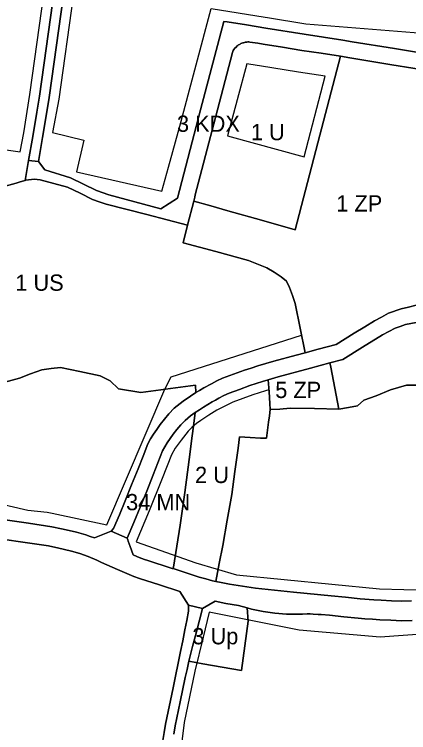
# Model space of a CAD drawing. Extents: x -294445 to -292055, y 21869 to 23693.
# Drawn here: x -293330.1 to -293087.7, y 22598.3 to 23039.5 of the extents above; entities that cross this region are included whole.
import ezdxf

# ---------------------------------------------------------------- set-up
doc = ezdxf.new("R2010")
doc.units = 0
for name, color, linetype in [('linie_rozgraniczajace', 7, 'Continuous'), ('linie_zabudowy_nieprzekraczalne', 7, 'Continuous'), ('oznaczenia_przeznaczen', 7, 'Continuous')]:
    doc.layers.add(name, color=color, linetype=linetype)

msp = doc.modelspace()

# ---------------------------------------------------------------- linework, layer by layer
at = {"layer": 'linie_rozgraniczajace'}
for points in [[(-293299.907, 23051.384), (-293308.794, 22988.328), (-293310.369, 22978.417), (-293312.858, 22963.757), (-293315.346, 22949.098), (-293321.333, 22949.685), (-293318.811, 22964.538), (-293316.29, 22979.39), (-293315.505, 22984.33), (-293314.72, 22989.27), (-293296.941, 23115.409)], [(-293296.941, 23115.409), (-293314.72, 22989.27), (-293315.505, 22984.33)], [(-293315.346, 22949.098), (-293312.858, 22963.757), (-293310.369, 22978.417), (-293308.794, 22988.328), (-293299.907, 23051.384)], [(-293072.139, 23004.28), (-293098.053, 23008.549), (-293123.966, 23012.819), (-293129.58, 23013.76), (-293141.588, 23015.576), (-293153.433, 23017.368), (-293165.307, 23019.257), (-293177.181, 23021.146), (-293180.425, 23021.669), (-293185.357, 23022.463), (-293185.862, 23022.492), (-293186.493, 23022.495), (-293187.11, 23022.463), (-293187.619, 23022.41), (-293188.16, 23022.327), (-293188.712, 23022.213), (-293189.312, 23022.054), (-293189.749, 23021.916), (-293190.346, 23021.692), (-293190.816, 23021.488), (-293191.304, 23021.246), (-293191.762, 23020.991), (-293192.213, 23020.71), (-293192.663, 23020.399), (-293193.264, 23019.925), (-293193.841, 23019.401), (-293194.562, 23018.626), (-293195.179, 23017.82), (-293195.5, 23017.331), (-293196.032, 23016.062), (-293207.469, 22972.314), (-293218.907, 22928.567), (-293219.18, 22927.093), (-293219.791, 22924.751), (-293223.618, 22910.077), (-293248.678, 22916.484), (-293273.738, 22922.891), (-293277.877, 22924.344), (-293282.015, 22925.798), (-293289.706, 22929.574), (-293297.396, 22933.35), (-293305.808, 22935.631), (-293314.22, 22937.911), (-293318.038, 22938.254), (-293323.044, 22937.614), (-293323.401, 22937.5), (-293321.333, 22949.685), (-293315.346, 22949.098), (-293311.352, 22943.884), (-293295.567, 22939.136), (-293279.691, 22931.341), (-293271.954, 22928.623), (-293256.017, 22924.284), (-293240.08, 22919.945), (-293229.779, 22926.514), (-293215.575, 22980.847), (-293201.37, 23035.18), (-293199.29, 23034.84), (-293187.445, 23032.93), (-293175.6, 23031.02), (-293151.9, 23027.25), (-293140.035, 23025.455), (-293128.17, 23023.66), (-293122.34, 23022.686), (-293096.315, 23018.398), (-293070.29, 23014.11)], [(-293070.29, 23014.11), (-293096.315, 23018.398), (-293122.34, 23022.686), (-293128.17, 23023.66), (-293140.035, 23025.455), (-293151.9, 23027.25), (-293175.6, 23031.02), (-293187.445, 23032.93), (-293199.29, 23034.84), (-293201.37, 23035.18), (-293215.575, 22980.847), (-293229.779, 22926.514), (-293240.08, 22919.945)], [(-293083.185, 22860.868), (-293087.721, 22859.716), (-293092.258, 22858.563), (-293100.066, 22855.873), (-293104.396, 22853.543), (-293108.726, 22851.213), (-293114.654, 22847.572), (-293121.122, 22843.625), (-293126.692, 22840.191), (-293132.263, 22836.757), (-293137.795, 22835.263), (-293143.327, 22833.768), (-293151.408, 22831.585), (-293154.424, 22846.682), (-293157.44, 22861.778), (-293159.206, 22866.785), (-293160.972, 22871.791), (-293162.756, 22875.604), (-293165.988, 22878.344), (-293170.455, 22881.018), (-293174.922, 22883.692), (-293186.082, 22888.209), (-293206.167, 22893.715), (-293226.252, 22899.222), (-293223.618, 22910.077), (-293219.791, 22924.751), (-293209.37, 22921.816), (-293198.95, 22918.88), (-293178.196, 22913.033), (-293157.442, 22907.187), (-293143.511, 22960.473), (-293129.58, 23013.76), (-293123.966, 23012.819), (-293098.053, 23008.549), (-293072.139, 23004.28)], [(-293315.505, 22984.33), (-293316.29, 22979.39), (-293318.811, 22964.538), (-293321.333, 22949.685), (-293323.401, 22937.5), (-293325.094, 22936.964), (-293327.145, 22936.313), (-293328.905, 22935.847), (-293344.144, 22931.667)], [(-293240.08, 22919.945), (-293256.017, 22924.284), (-293271.954, 22928.623), (-293279.691, 22931.341), (-293295.567, 22939.136), (-293311.352, 22943.884), (-293315.346, 22949.098)], [(-293344.144, 22931.667), (-293328.905, 22935.847), (-293327.145, 22936.313), (-293325.094, 22936.964), (-293323.401, 22937.5), (-293323.044, 22937.614), (-293318.038, 22938.254), (-293314.22, 22937.911), (-293305.808, 22935.631), (-293297.396, 22933.35), (-293289.706, 22929.574), (-293282.015, 22925.798), (-293277.877, 22924.344), (-293273.738, 22922.891), (-293248.678, 22916.484), (-293223.618, 22910.077), (-293226.252, 22899.222), (-293206.167, 22893.715), (-293186.082, 22888.209), (-293174.922, 22883.692), (-293170.455, 22881.018), (-293165.988, 22878.344), (-293162.756, 22875.604), (-293160.972, 22871.791), (-293159.206, 22866.785), (-293157.44, 22861.778), (-293154.424, 22846.682), (-293151.408, 22831.585), (-293156.938, 22830.092), (-293170.549, 22826.415), (-293175.484, 22824.977), (-293180.419, 22823.54), (-293184.509, 22822.216), (-293188.598, 22820.893), (-293195.387, 22818.436), (-293202.175, 22815.98), (-293205.576, 22814.306), (-293208.978, 22812.632), (-293213.612, 22810.11), (-293216.368, 22808.453), (-293218.479, 22807.184), (-293218.736, 22811.745), (-293227.936, 22810.516), (-293237.137, 22809.286), (-293240.04, 22808.898), (-293246.17, 22808.079), (-293252.3, 22807.26), (-293266.04, 22809.54), (-293271.31, 22814.28), (-293276.85, 22817.26), (-293277.457, 22817.39), (-293289.867, 22820.05), (-293301.67, 22822.58), (-293307.475, 22821.905), (-293313.28, 22821.23), (-293320.105, 22818.67), (-293326.93, 22816.11), (-293336.05, 22813.51)], [(-293075.467, 22851.666), (-293089.654, 22848.884), (-293092.848, 22847.783), (-293096.041, 22846.682), (-293099.889, 22844.612), (-293103.736, 22842.542), (-293115.998, 22835.011), (-293128.26, 22827.48), (-293136.065, 22825.372), (-293148.053, 22822.133), (-293167.847, 22816.787), (-293174.092, 22814.967), (-293177.48, 22813.98), (-293181.42, 22812.705), (-293185.36, 22811.43), (-293191.735, 22809.128), (-293198.109, 22806.827), (-293201.246, 22805.287), (-293204.383, 22803.747), (-293206.489, 22802.601), (-293208.595, 22801.455), (-293211.17, 22799.868), (-293213.746, 22798.28), (-293216.359, 22796.627), (-293218.971, 22794.974), (-293221.86, 22792.792), (-293225.047, 22790.109), (-293227.792, 22787.436), (-293230.183, 22784.397), (-293232.453, 22781.514), (-293234.33, 22778.876), (-293236.207, 22776.238), (-293238.962, 22771.453), (-293241.85, 22764.004), (-293244.684, 22756.689), (-293248.759, 22746.687), (-293252.781, 22736.818), (-293256.753, 22727.285), (-293260.726, 22717.753), (-293270.514, 22722.067), (-293269.08, 22723.62), (-293265.555, 22732.12), (-293262.03, 22740.62), (-293258.03, 22750.435), (-293254.03, 22760.25), (-293251.02, 22768.015), (-293248.01, 22775.78), (-293246.322, 22778.712), (-293244.634, 22781.644), (-293242.547, 22784.576), (-293240.461, 22787.509), (-293237.851, 22790.824), (-293235.241, 22794.139), (-293231.765, 22797.526), (-293226.383, 22801.907), (-293221.896, 22805), (-293218.479, 22807.184), (-293216.368, 22808.453), (-293213.612, 22810.11), (-293208.978, 22812.632), (-293205.576, 22814.306), (-293202.175, 22815.98), (-293195.387, 22818.436), (-293188.598, 22820.893), (-293184.509, 22822.216), (-293180.419, 22823.54), (-293175.484, 22824.977), (-293170.549, 22826.415), (-293156.938, 22830.092), (-293151.408, 22831.585), (-293143.327, 22833.768), (-293137.795, 22835.263), (-293132.263, 22836.757), (-293126.692, 22840.191), (-293121.122, 22843.625), (-293114.654, 22847.572), (-293108.726, 22851.213), (-293104.396, 22853.543), (-293100.066, 22855.873), (-293092.258, 22858.563), (-293087.721, 22859.716), (-293083.185, 22860.868)], [(-293073.705, 22811.635), (-293088.99, 22811.74), (-293093.955, 22810.25), (-293098.92, 22808.76), (-293107.63, 22805.24), (-293115.26, 22802.57), (-293119.21, 22799.03), (-293124.787, 22798.069), (-293130.7, 22797.05), (-293133.128, 22809.866), (-293135.555, 22822.681), (-293136.065, 22825.372), (-293128.26, 22827.48), (-293115.998, 22835.011), (-293103.736, 22842.542), (-293099.889, 22844.612), (-293096.041, 22846.682), (-293092.848, 22847.783), (-293089.654, 22848.884), (-293075.467, 22851.666)], [(-293336.05, 22813.51), (-293326.93, 22816.11), (-293320.105, 22818.67), (-293313.28, 22821.23), (-293307.475, 22821.905), (-293301.67, 22822.58), (-293289.867, 22820.05), (-293277.457, 22817.39), (-293276.85, 22817.26), (-293271.31, 22814.28), (-293266.04, 22809.54), (-293252.3, 22807.26), (-293246.17, 22808.079), (-293240.04, 22808.898), (-293237.137, 22809.286), (-293227.936, 22810.516), (-293218.736, 22811.745), (-293218.479, 22807.184), (-293221.896, 22805), (-293226.383, 22801.907), (-293231.765, 22797.526), (-293235.241, 22794.139), (-293237.851, 22790.824), (-293240.461, 22787.509), (-293242.547, 22784.576), (-293244.634, 22781.644), (-293246.322, 22778.712), (-293248.01, 22775.78), (-293251.02, 22768.015), (-293254.03, 22760.25), (-293258.03, 22750.435), (-293262.03, 22740.62), (-293265.555, 22732.12), (-293269.08, 22723.62), (-293270.514, 22722.067), (-293280.834, 22717.853), (-293283.499, 22718.812), (-293286.164, 22719.771), (-293289.031, 22720.589), (-293291.898, 22721.408), (-293296.508, 22722.481), (-293301.118, 22723.555), (-293307.173, 22724.755), (-293321.52, 22726.874), (-293335.867, 22728.994)], [(-293085.91, 22679.252), (-293092.014, 22678.982), (-293098.318, 22679.308), (-293104.621, 22679.634), (-293109.18, 22679.939), (-293117.611, 22680.561), (-293126.439, 22681.427), (-293135.266, 22682.292), (-293158.562, 22684.617), (-293181.859, 22686.942), (-293189.874, 22688.208), (-293197.889, 22689.475), (-293203.056, 22690.554), (-293206.234, 22691.217), (-293204.112, 22702.249), (-293201.99, 22713.28), (-293199.235, 22728.89), (-293196.48, 22744.5), (-293194.47, 22758.75), (-293192.46, 22773), (-293191.66, 22779.94), (-293185.2, 22779.565), (-293178.74, 22779.19), (-293175, 22779.063), (-293174.424, 22783.988), (-293173.848, 22788.914), (-293173.341, 22792.8), (-293172.834, 22796.686), (-293167, 22796.99), (-293160.63, 22797.53), (-293145.665, 22797.29), (-293130.7, 22797.05), (-293124.787, 22798.069), (-293119.21, 22799.03), (-293115.26, 22802.57), (-293107.63, 22805.24), (-293098.92, 22808.76), (-293093.955, 22810.25), (-293088.99, 22811.74), (-293073.705, 22811.635)], [(-293335.867, 22728.994), (-293321.52, 22726.874), (-293307.173, 22724.755), (-293301.118, 22723.555), (-293296.508, 22722.481), (-293291.898, 22721.408), (-293289.031, 22720.589), (-293286.164, 22719.771), (-293283.499, 22718.812), (-293280.834, 22717.853), (-293270.514, 22722.067), (-293260.726, 22717.753), (-293260.391, 22716.791), (-293260.062, 22715.847), (-293258.934, 22712.607), (-293257.142, 22707.461), (-293254.754, 22706.424), (-293252.365, 22705.387), (-293249.567, 22704.424), (-293248.658, 22704.135), (-293232.999, 22699.147), (-293232.562, 22699.008), (-293216.43, 22693.869), (-293212.327, 22692.751), (-293208.224, 22691.633), (-293206.234, 22691.217), (-293203.056, 22690.554), (-293197.889, 22689.475), (-293189.874, 22688.208), (-293181.859, 22686.942), (-293158.562, 22684.617), (-293135.266, 22682.292), (-293126.439, 22681.427), (-293117.611, 22680.561), (-293109.18, 22679.939), (-293104.621, 22679.634), (-293098.318, 22679.308), (-293092.014, 22678.982), (-293085.91, 22679.252)], [(-293337.519, 22717.108), (-293323.368, 22715.017), (-293309.217, 22712.927), (-293306.431, 22712.375), (-293303.646, 22711.823), (-293299.277, 22710.805), (-293294.908, 22709.788), (-293289.846, 22708.342), (-293284.646, 22706.471), (-293279.467, 22704.171), (-293276.533, 22702.798), (-293266.623, 22698.495), (-293256.713, 22694.192), (-293253.258, 22693.004), (-293240.791, 22689.03), (-293228.323, 22685.055), (-293223.055, 22676.544), (-293223.01, 22672.81), (-293224.157, 22667.084), (-293225.304, 22661.357), (-293226.63, 22654.739), (-293227.955, 22648.12), (-293232.563, 22625.817), (-293237.17, 22603.514), (-293238.035, 22598.462), (-293238.9, 22593.41)], [(-293085.501, 22667.258), (-293092.059, 22666.968), (-293098.695, 22667.311), (-293105.332, 22667.654), (-293109.981, 22667.966), (-293114.629, 22668.277), (-293118.687, 22668.609), (-293127.567, 22669.48), (-293136.447, 22670.351), (-293141.395, 22670.752), (-293143.281, 22670.906), (-293146.343, 22671.154), (-293148.233, 22671.195), (-293150.123, 22671.236), (-293152.868, 22671.137), (-293155.612, 22671.039), (-293162.881, 22671.09), (-293170.004, 22671.678), (-293177.084, 22672.727), (-293184.226, 22674.155), (-293186.99, 22674.94), (-293192.322, 22676.446), (-293196.188, 22677.057), (-293200.053, 22677.668), (-293206.565, 22679.028), (-293214.541, 22674.444), (-293223.055, 22676.544), (-293228.323, 22685.055), (-293240.791, 22689.03), (-293253.258, 22693.004), (-293256.713, 22694.192), (-293266.623, 22698.495), (-293276.533, 22702.798), (-293279.467, 22704.171), (-293284.646, 22706.471), (-293289.846, 22708.342), (-293294.908, 22709.788), (-293299.277, 22710.805), (-293303.646, 22711.823), (-293306.431, 22712.375), (-293309.217, 22712.927), (-293323.368, 22715.017), (-293337.519, 22717.108)], [(-293238.9, 22593.41), (-293238.035, 22598.462), (-293237.17, 22603.514), (-293232.563, 22625.817), (-293227.955, 22648.12), (-293226.63, 22654.739), (-293225.304, 22661.357), (-293224.157, 22667.084), (-293223.01, 22672.81), (-293223.055, 22676.544), (-293214.541, 22674.444), (-293218.224, 22660.111), (-293220.497, 22651.11), (-293222.77, 22642.11), (-293223.934, 22637.12), (-293225.097, 22632.131), (-293228.186, 22617.266), (-293231.274, 22602.401), (-293232.126, 22597.42)], [(-293232.126, 22597.42), (-293231.274, 22602.401), (-293228.186, 22617.266), (-293225.097, 22632.131), (-293223.934, 22637.12), (-293222.77, 22642.11), (-293214.15, 22640.61), (-293202.265, 22638.535), (-293190.38, 22636.46), (-293188.335, 22651.56), (-293186.29, 22666.66), (-293186.99, 22674.94), (-293184.226, 22674.155), (-293177.084, 22672.727), (-293170.004, 22671.678), (-293162.881, 22671.09), (-293155.612, 22671.039), (-293152.868, 22671.137), (-293150.123, 22671.236), (-293148.233, 22671.195), (-293146.343, 22671.154), (-293143.281, 22670.906), (-293141.395, 22670.752), (-293136.447, 22670.351), (-293127.567, 22669.48), (-293118.687, 22668.609), (-293114.629, 22668.277), (-293109.981, 22667.966), (-293105.332, 22667.654), (-293098.695, 22667.311), (-293092.059, 22666.968), (-293085.501, 22667.258)]]:
    msp.add_lwpolyline(points, dxfattribs=at)
for points in [[(-293219.791, 22924.751), (-293219.18, 22927.093), (-293218.907, 22928.567), (-293207.469, 22972.314), (-293196.032, 23016.062), (-293195.5, 23017.331), (-293195.179, 23017.82), (-293194.562, 23018.626), (-293193.841, 23019.401), (-293193.264, 23019.925), (-293192.663, 23020.399), (-293192.213, 23020.71), (-293191.762, 23020.991), (-293191.304, 23021.246), (-293190.816, 23021.488), (-293190.346, 23021.692), (-293189.749, 23021.916), (-293189.312, 23022.054), (-293188.712, 23022.213), (-293188.16, 23022.327), (-293187.619, 23022.41), (-293187.11, 23022.463), (-293186.493, 23022.495), (-293185.862, 23022.492), (-293185.357, 23022.463), (-293180.425, 23021.669), (-293177.181, 23021.146), (-293165.307, 23019.257), (-293153.433, 23017.368), (-293141.588, 23015.576), (-293129.58, 23013.76), (-293143.511, 22960.473), (-293157.442, 22907.187), (-293178.196, 22913.033), (-293198.95, 22918.88), (-293209.37, 22921.816)], [(-293174.092, 22814.967), (-293167.847, 22816.787), (-293148.053, 22822.133), (-293136.065, 22825.372), (-293135.555, 22822.681), (-293133.128, 22809.866), (-293130.7, 22797.05), (-293145.665, 22797.29), (-293160.63, 22797.53), (-293167, 22796.99), (-293172.834, 22796.686), (-293173.03, 22800.45), (-293173.561, 22807.708)], [(-293232.562, 22699.008), (-293232.29, 22699.92), (-293230.185, 22712.79), (-293228.08, 22725.66), (-293225.33, 22745.855), (-293222.58, 22766.05), (-293220.776, 22780.512), (-293220.017, 22786.594), (-293218.971, 22794.974), (-293216.359, 22796.627), (-293213.746, 22798.28), (-293211.17, 22799.868), (-293208.595, 22801.455), (-293206.489, 22802.601), (-293204.383, 22803.747), (-293201.246, 22805.287), (-293198.109, 22806.827), (-293191.735, 22809.128), (-293185.36, 22811.43), (-293181.42, 22812.705), (-293177.48, 22813.98), (-293174.092, 22814.967), (-293173.561, 22807.708), (-293173.03, 22800.45), (-293172.834, 22796.686), (-293173.341, 22792.8), (-293173.848, 22788.914), (-293174.424, 22783.988), (-293175, 22779.063), (-293178.74, 22779.19), (-293185.2, 22779.565), (-293191.66, 22779.94), (-293192.46, 22773), (-293194.47, 22758.75), (-293196.48, 22744.5), (-293199.235, 22728.89), (-293201.99, 22713.28), (-293204.112, 22702.249), (-293206.234, 22691.217), (-293208.224, 22691.633), (-293212.327, 22692.751), (-293216.43, 22693.869)], [(-293260.726, 22717.753), (-293256.753, 22727.285), (-293252.781, 22736.818), (-293248.759, 22746.687), (-293244.684, 22756.689), (-293241.85, 22764.004), (-293238.962, 22771.453), (-293236.207, 22776.238), (-293234.33, 22778.876), (-293232.453, 22781.514), (-293230.183, 22784.397), (-293227.792, 22787.436), (-293225.047, 22790.109), (-293221.86, 22792.792), (-293218.971, 22794.974), (-293220.017, 22786.594), (-293220.776, 22780.512), (-293222.58, 22766.05), (-293225.33, 22745.855), (-293228.08, 22725.66), (-293230.185, 22712.79), (-293232.29, 22699.92), (-293232.562, 22699.008), (-293232.999, 22699.147), (-293248.658, 22704.135), (-293249.567, 22704.424), (-293252.365, 22705.387), (-293254.754, 22706.424), (-293257.142, 22707.461), (-293258.934, 22712.607), (-293260.062, 22715.847), (-293260.391, 22716.791)], [(-293222.77, 22642.11), (-293220.497, 22651.11), (-293218.224, 22660.111), (-293214.541, 22674.444), (-293206.565, 22679.028), (-293200.053, 22677.668), (-293196.188, 22677.057), (-293192.322, 22676.446), (-293186.99, 22674.94), (-293186.29, 22666.66), (-293188.335, 22651.56), (-293190.38, 22636.46), (-293202.265, 22638.535), (-293214.15, 22640.61)]]:
    msp.add_lwpolyline(points, close=True, dxfattribs=at)
at = {"layer": 'linie_zabudowy_nieprzekraczalne'}
for points in [[(-293324.378, 22966.773), (-293320.654, 22990.16), (-293302.908, 23116.063)], [(-293285.056, 23113.767), (-293302.86, 22987.439), (-293306.681, 22966.878), (-293287.499, 22962.283), (-293291.884, 22942.735), (-293239.404, 22930.893), (-293235.383, 22945.584), (-293228.475, 22970.823), (-293209.126, 23043.154), (-293175.962, 23037.665), (-293174.572, 23037.441), (-293150.903, 23033.676), (-293048.406, 23025.552), (-293047.321, 23037.206), (-292997.632, 23031.638), (-292998.715, 23056.491)], [(-293138.979, 23001.53), (-293155.503, 23004.03), (-293179.316, 23007.818), (-293180.799, 23008.057), (-293187.177, 23009.113), (-293198.986, 22964.935), (-293198.986, 22964.935), (-293151.936, 22951.969), (-293138.979, 23001.53)], [(-293465.55, 22962.26), (-293379.27, 22939.592), (-293370.366, 22938.454), (-293349.174, 22943.549), (-293346.743, 22957.909), (-293326.535, 22955.071), (-293324.378, 22966.773)], [(-293391.809, 22751.051), (-293321.855, 22735.037), (-293309.877, 22733.665), (-293306.952, 22733.025), (-293306.952, 22733.025), (-293306.952, 22733.025), (-293273.338, 22725.909), (-293237.579, 22809.227), (-293233.685, 22816.802), (-293153.556, 22842.336)], [(-293173.645, 22808.848), (-293175.717, 22808.244), (-293183.417, 22805.752), (-293195.762, 22801.295), (-293201.626, 22798.417), (-293205.584, 22796.263), (-293210.568, 22793.191), (-293215.553, 22790.036), (-293218.117, 22788.1), (-293221.017, 22785.659), (-293223.322, 22783.414), (-293227.649, 22777.917), (-293231.151, 22772.994), (-293233.534, 22768.856), (-293239.161, 22754.339), (-293247.234, 22734.531), (-293255.187, 22715.445), (-293218.623, 22702.515), (-293193.619, 22695.116), (-293105.609, 22686.547), (-293060.776, 22685.477)], [(-292936.995, 22669.768), (-293045.22, 22661.37), (-293076.999, 22659.077), (-293105.235, 22656.962), (-293155, 22661.193), (-293210.447, 22672.251), (-293214.074, 22656.903), (-293219.194, 22636.013), (-293219.194, 22636.013), (-293225.657, 22604.489), (-293225.657, 22604.489), (-293228.151, 22584.509)]]:
    msp.add_lwpolyline(points, dxfattribs=at)

# ---------------------------------------------------------------- texts
at = {"layer": 'oznaczenia_przeznaczen'}
for s, p in [('3 KDX', (-293230.12, 22967.314)), ('1 U', (-293184.699, 22962.139)), ('1 ZP', (-293132.187, 22918.353)), ('1 US', (-293329.514, 22869.684)), ('5 ZP', (-293169.714, 22803.801)), ('2 U', (-293219.024, 22751.594)), ('34 MN', (-293261.419, 22734.894)), ('3 Up', (-293220.68, 22652.537))]:
    msp.add_text(s, height=10, dxfattribs=at).set_placement(p)

doc.saveas('drawing.dxf')
